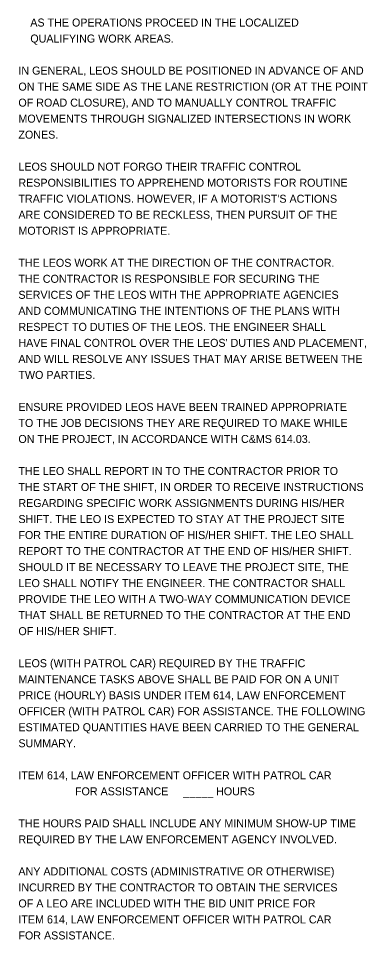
# Model space of a CAD drawing. Extents: x -36 to 68, y -39 to 86.
# Drawn here: x 53.24 to 59.34, y -39.4 to -23.3 of the extents above; entities that cross this region are included whole.
import ezdxf

# ---------------------------------------------------------------- set-up
doc = ezdxf.new("R2010")
doc.units = 0
doc.layers.add('SH_Text', color=7, linetype='Continuous')

msp = doc.modelspace()

# ---------------------------------------------------------------- texts
at = {"layer": 'SH_Text'}
for s, p in [('    AS THE OPERATIONS PROCEED IN THE LOCALIZED', (53.24, -23.44)), ('    QUALIFYING WORK AREAS.', (53.24, -23.72)), ('IN GENERAL, LEOS SHOULD BE POSITIONED IN ADVANCE OF AND', (53.24, -24.28)), ('ON THE SAME SIDE AS THE LANE RESTRICTION (OR AT THE POINT', (53.24, -24.56)), ('OF ROAD CLOSURE), AND TO MANUALLY CONTROL TRAFFIC', (53.24, -24.84)), ('MOVEMENTS THROUGH SIGNALIZED INTERSECTIONS IN WORK', (53.24, -25.12)), ('ZONES.', (53.24, -25.4)), ('LEOS SHOULD NOT FORGO THEIR TRAFFIC CONTROL', (53.24, -25.96)), ('RESPONSIBILITIES TO APPREHEND MOTORISTS FOR ROUTINE', (53.24, -26.24)), ("TRAFFIC VIOLATIONS. HOWEVER, IF A MOTORIST'S ACTIONS", (53.24, -26.52)), ('ARE CONSIDERED TO BE RECKLESS, THEN PURSUIT OF THE', (53.24, -26.8)), ('MOTORIST IS APPROPRIATE.', (53.24, -27.08)), ('THE LEOS WORK AT THE DIRECTION OF THE CONTRACTOR.', (53.24, -27.64)), ('THE CONTRACTOR IS RESPONSIBLE FOR SECURING THE', (53.24, -27.92)), ('SERVICES OF THE LEOS WITH THE APPROPRIATE AGENCIES', (53.24, -28.2)), ('AND COMMUNICATING THE INTENTIONS OF THE PLANS WITH', (53.24, -28.48)), ('RESPECT TO DUTIES OF THE LEOS. THE ENGINEER SHALL', (53.24, -28.76)), ("HAVE FINAL CONTROL OVER THE LEOS' DUTIES AND PLACEMENT,", (53.24, -29.04)), ('AND WILL RESOLVE ANY ISSUES THAT MAY ARISE BETWEEN THE', (53.24, -29.32)), ('TWO PARTIES.', (53.24, -29.6)), ('ENSURE PROVIDED LEOS HAVE BEEN TRAINED APPROPRIATE', (53.24, -30.16)), ('TO THE JOB DECISIONS THEY ARE REQUIRED TO MAKE WHILE', (53.24, -30.44)), ('ON THE PROJECT, IN ACCORDANCE WITH C&MS 614.03.', (53.24, -30.72)), ('THE LEO SHALL REPORT IN TO THE CONTRACTOR PRIOR TO', (53.24, -31.28)), ('THE START OF THE SHIFT, IN ORDER TO RECEIVE INSTRUCTIONS', (53.24, -31.56)), ('REGARDING SPECIFIC WORK ASSIGNMENTS DURING HIS/HER', (53.24, -31.84)), ('SHIFT. THE LEO IS EXPECTED TO STAY AT THE PROJECT SITE', (53.24, -32.12)), ('FOR THE ENTIRE DURATION OF HIS/HER SHIFT. THE LEO SHALL', (53.24, -32.4)), ('REPORT TO THE CONTRACTOR AT THE END OF HIS/HER SHIFT.', (53.24, -32.68)), ('SHOULD IT BE NECESSARY TO LEAVE THE PROJECT SITE, THE', (53.24, -32.96)), ('LEO SHALL NOTIFY THE ENGINEER. THE CONTRACTOR SHALL', (53.24, -33.24)), ('PROVIDE THE LEO WITH A TWO-WAY COMMUNICATION DEVICE', (53.24, -33.52)), ('THAT SHALL BE RETURNED TO THE CONTRACTOR AT THE END', (53.24, -33.8)), ('OF HIS/HER SHIFT.', (53.24, -34.08)), ('LEOS (WITH PATROL CAR) REQUIRED BY THE TRAFFIC', (53.24, -34.64)), ('MAINTENANCE TASKS ABOVE SHALL BE PAID FOR ON A UNIT', (53.24, -34.92)), ('PRICE (HOURLY) BASIS UNDER ITEM 614, LAW ENFORCEMENT', (53.24, -35.2)), ('OFFICER (WITH PATROL CAR) FOR ASSISTANCE. THE FOLLOWING', (53.24, -35.48)), ('ESTIMATED QUANTITIES HAVE BEEN CARRIED TO THE GENERAL', (53.24, -35.76)), ('SUMMARY.', (53.24, -36.04)), ('ITEM 614, LAW ENFORCEMENT OFFICER WITH PATROL CAR', (53.24, -36.6)), ('                   FOR ASSISTANCE     _____ HOURS', (53.24, -36.88)), ('THE HOURS PAID SHALL INCLUDE ANY MINIMUM SHOW-UP TIME', (53.24, -37.44)), ('REQUIRED BY THE LAW ENFORCEMENT AGENCY INVOLVED.', (53.24, -37.72)), ('ANY ADDITIONAL COSTS (ADMINISTRATIVE OR OTHERWISE)', (53.24, -38.28)), ('INCURRED BY THE CONTRACTOR TO OBTAIN THE SERVICES', (53.24, -38.56)), ('OF A LEO ARE INCLUDED WITH THE BID UNIT PRICE FOR', (53.24, -38.84)), ('ITEM 614, LAW ENFORCEMENT OFFICER WITH PATROL CAR', (53.24, -39.12)), ('FOR ASSISTANCE.', (53.24, -39.4))]:
    msp.add_text(s, height=0.14, dxfattribs=at).set_placement(p)

doc.saveas('drawing.dxf')
